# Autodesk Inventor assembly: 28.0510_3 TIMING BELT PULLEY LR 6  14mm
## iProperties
Created: 2007-06
Part Number: 28.0510_3 TIMING BELT PULLEY LR 6  14mm
Document SubType Name: Assembly
Designer: Andy Moles
Author: Andy Moles
